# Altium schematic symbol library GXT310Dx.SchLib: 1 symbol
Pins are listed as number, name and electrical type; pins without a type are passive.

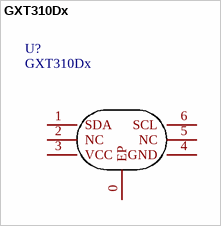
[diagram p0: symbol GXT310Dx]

## GXT310Dx
designator U?
footprint QFN6-EP(2*2*0.75) P=0.5
pins: 0 EP, 1 SDA, 2 NC, 3 VCC, 4 GND, 5 NC, 6 SCL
